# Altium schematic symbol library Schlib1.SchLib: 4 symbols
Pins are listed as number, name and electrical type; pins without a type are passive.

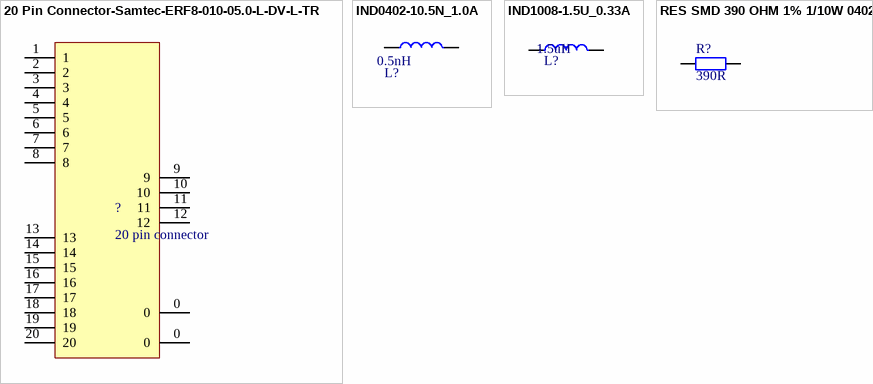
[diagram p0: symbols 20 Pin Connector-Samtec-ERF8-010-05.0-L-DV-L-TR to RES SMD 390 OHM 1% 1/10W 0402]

## 20 Pin Connector-Samtec-ERF8-010-05.0-L-DV-L-TR
designator ?, comment 20 pin connector
20 Pin Connector-Samtec-ERF8-010-05.0-L-DV-L-TR; Manufacturer: Samtec; Tech: SMDR
footprint 20-pin-connector (ERF8-010-05.0-L-DV-L-TR)
pins: 0, 0, 1, 2, 3, 4, 5, 6, 7, 8, 9, 10, 11, 12, 13, 14, 15, 16, 17, 18, 19, 20
1 alternate drawing of the same symbol

## IND0402-10.5N_1.0A
designator L?, comment 0.5nH
Chip inductor 0402 1.0A 100mR; Manufacturer: TDK; Manufacturer No: MLG1005S0N5CT000; Tech: SMDR
signal-integrity model Model Name (Model Description)
footprint LC0402N1X (Chip inductor 0402)
footprint LC0402N1R (Chip inductor 0402 ROUNDED PAD)
pins: 1, 2

## IND1008-1.5U_0.33A
designator L?, comment 1.5uH
Chip inductor 1008 0.33A 2.3R; Manufacturer: Coilcraft; Manufacturer No: 1008CS-152XJLB; Tech: SMDR
signal-integrity model Model Name (Model Description)
footprint LC1008CS (Chip Inductor, 2-Leads, Body 2,92x2,79mm, IPC Medium Density)
pins: 1, 2

## RES SMD 390 OHM 1% 1/10W 0402
designator R?, comment 390R
Chip Resistor 0402 0.1mW 1% 100ppm; Manufacturer: Panasonic; Manufacturer No: ERJ-2RKF3900X; Tech: SMDR
simulation model RESISTOR (Resistor)
signal-integrity model Res
footprint RC0402N1R (Chip capacitor 0402 ROUNDED PAD)
footprint RC0402N1X (Chip capacitor 0402)
footprint RC0402RF1 (Chip resistor 0402 RF pad)
footprint RC0402RF1R (Chip resistor 0402 RF round pad)
pins: 1, 2
1 alternate drawing of the same symbol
